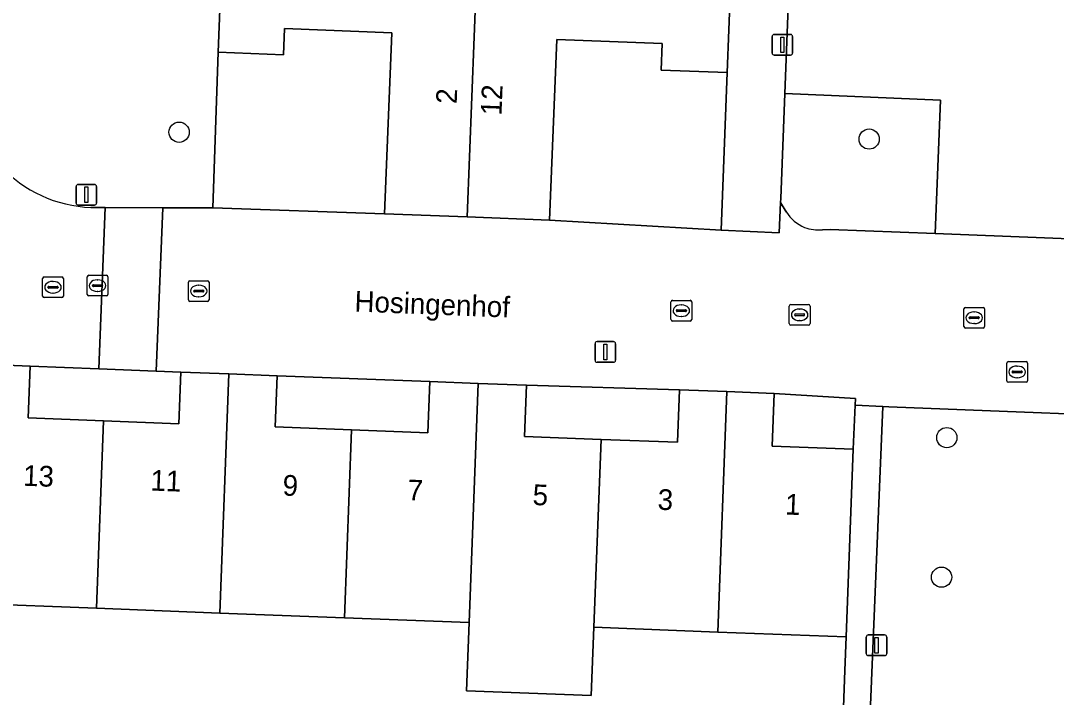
# Model space of a CAD drawing. Extents: x 160786 to 161429, y 386828 to 387485.
# Drawn here: x 161233.9 to 161283.9, y 387191.8 to 387224.5 of the extents above; entities that cross this region are included whole.
import ezdxf

# ---------------------------------------------------------------- set-up
doc = ezdxf.new("R2010")
doc.units = 0
for name, color, linetype in [('IMGEO_Boom', 7, 'Continuous'), ('IMGEO_Brandkraan', 7, 'Continuous'), ('IMGEO_Erf', 7, 'Continuous'), ('IMGEO_Groenvoorziening', 7, 'Continuous'), ('IMGEO_Kolk', 7, 'Continuous'), ('IMGEO_Lichtmast', 7, 'Continuous'), ('IMGEO_Muur', 7, 'Continuous'), ('IMGEO_Openbare_ruimte_label', 7, 'Continuous'), ('IMGEO_Pand', 7, 'Continuous'), ('IMGEO_Pand_nummerreeks', 7, 'Continuous'), ('IMGEO_Rijbaan_lokaal_open', 7, 'Continuous'), ('IMGEO_Rioolput', 7, 'Continuous'), ('IMGEO_Voetpad_open', 7, 'Continuous')]:
    doc.layers.add(name, color=color, linetype=linetype)

msp = doc.modelspace()

# ---------------------------------------------------------------- linework, layer by layer
at = {"layer": 'IMGEO_Boom'}
for centre in [(161241.538, 387219.106), (161274.878, 387218.776), (161278.63, 387204.353), (161278.378, 387197.612)]:
    msp.add_circle(centre, 0.489, dxfattribs=at)
at = {"layer": 'IMGEO_Brandkraan'}
for p, q in [((161281.606, 387208.028), (161282.458, 387208.028)), ((161281.531, 387207.102), (161281.531, 387207.954)), ((161281.79, 387207.522), (161281.79, 387207.534)), ((161281.833, 387207.571), (161282.231, 387207.571)), ((161282.019, 387207.808), (161282.044, 387207.808)), ((161282.274, 387207.534), (161282.274, 387207.522)), ((161282.532, 387207.954), (161282.532, 387207.102)), ((161282.458, 387207.028), (161281.606, 387207.028)), ((161282.228, 387207.485), (161281.83, 387207.485)), ((161282.042, 387207.248), (161282.017, 387207.248))]:
    msp.add_line(p, q, dxfattribs=at)
for points in [[(161281.606, 387208.028), (161282.458, 387208.028)], [(161281.531, 387207.102), (161281.531, 387207.954)], [(161282.532, 387207.954), (161282.532, 387207.102)], [(161282.458, 387207.028), (161281.606, 387207.028)]]:
    msp.add_lwpolyline(points, dxfattribs=at)
for centre, radius, start, end in [((161281.608, 387207.952), 0.0765, 91.552, 178.448), ((161281.608, 387207.952), 0.0765, 91.552, 178.448), ((161282.456, 387207.952), 0.0765, 1.552, 88.448), ((161282.456, 387207.952), 0.0765, 1.552, 88.448), ((161281.83, 387207.531), 0.0403, 85.8775, 175.7526), ((161281.827, 387207.521), 0.0366, 178.938, 274.7102), ((161282.231, 387207.528), 0.043, 264.8664, 352.4533), ((161282.235, 387207.533), 0.0386, 1.7309, 96.639), ((161281.608, 387207.104), 0.0765, 181.552, 268.448), ((161281.608, 387207.104), 0.0765, 181.552, 268.448), ((161282.456, 387207.104), 0.0765, 271.552, 358.448), ((161282.456, 387207.104), 0.0765, 271.552, 358.448)]:
    msp.add_arc(centre, radius, start, end, dxfattribs=at)
for centre, major_axis, ratio, start_param, end_param in [((161282.018, 387207.528), (-0.387, 0.002), 0.722429, 4.712389, 7.853982), ((161282.043, 387207.528), (-0.39, 0.002), 0.717154, 1.570796, 4.712389)]:
    msp.add_ellipse(centre, major_axis=major_axis, ratio=ratio, start_param=start_param, end_param=end_param, dxfattribs=at)
at = {"layer": 'IMGEO_Erf'}
for points in [[(161243.165, 387215.454), (161251.463, 387215.171), (161251.811, 387223.912), (161246.634, 387224.118), (161246.584, 387222.846), (161243.425, 387222.972)], [(161268.013, 387221.984), (161264.831, 387222.111), (161264.882, 387223.389), (161259.784, 387223.592), (161259.437, 387214.853), (161267.73, 387214.375)], [(161237.659, 387207.677), (161234.345, 387207.807), (161234.25, 387205.304), (161237.885, 387205.165), (161241.52, 387205.027), (161241.615, 387207.521), (161240.436, 387207.567)], [(161246.271, 387207.343), (161246.177, 387204.869), (161249.87, 387204.728), (161253.563, 387204.587), (161253.658, 387207.063)], [(161258.322, 387206.886), (161258.228, 387204.411), (161261.925, 387204.27), (161265.618, 387204.13), (161265.715, 387206.665)], [(161274.202, 387205.923), (161274.217, 387206.248), (161270.296, 387206.49), (161270.199, 387203.947), (161274.106, 387203.798)]]:
    msp.add_lwpolyline(points, close=True, dxfattribs=at)
msp.add_lwpolyline([(161273.288, 387181.587), (161273.702, 387193.11), (161273.76, 387194.728), (161267.563, 387194.964), (161261.579, 387195.192), (161261.452, 387191.894), (161255.425, 387192.124), (161255.55, 387195.422), (161249.524, 387195.652), (161243.502, 387195.881), (161237.54, 387196.109), (161231.59, 387196.335)], dxfattribs=at)
at = {"layer": 'IMGEO_Groenvoorziening'}
for points in [[(161302.945, 387270.254), (161272.951, 387271.43), (161272.761, 387271.438), (161270.807, 387220.973), (161278.33, 387220.657), (161278.076, 387214.209), (161299.195, 387213.381)], [(161278.33, 387220.657), (161270.807, 387220.973), (161270.611, 387215.901), (161270.603, 387215.713), (161270.826, 387215.342), (161270.88, 387215.251)], [(161272.624, 387214.392), (161272.998, 387214.408), (161278.076, 387214.209), (161278.33, 387220.657)], [(161291.402, 387205.236), (161275.836, 387205.849), (161275.544, 387205.862), (161274.672, 387184.815), (161274.672, 387184.136), (161274.676, 387183.739), (161274.704, 387183.178)]]:
    msp.add_lwpolyline(points, dxfattribs=at)
for centre, radius, start, end in [((161272.497, 387216.271), 1.912, 212.2414, 247.1627), ((161272.456, 387216.432), 2.047, 249.9626, 274.7013)]:
    msp.add_arc(centre, radius, start, end, dxfattribs=at)
at = {"layer": 'IMGEO_Kolk'}
for p, q in [((161237.097, 387211.272), (161237.097, 387212.124)), ((161237.172, 387212.198), (161238.024, 387212.198)), ((161238.098, 387212.124), (161238.098, 387211.272)), ((161237.356, 387211.692), (161237.356, 387211.704)), ((161237.794, 387211.655), (161237.396, 387211.655)), ((161237.399, 387211.741), (161237.797, 387211.741)), ((161237.585, 387211.978), (161237.61, 387211.978)), ((161237.84, 387211.704), (161237.84, 387211.692)), ((161241.985, 387211.009), (161241.985, 387211.861)), ((161242.06, 387211.935), (161242.912, 387211.935)), ((161242.473, 387211.715), (161242.498, 387211.715)), ((161242.986, 387211.861), (161242.986, 387211.009)), ((161238.024, 387211.198), (161237.172, 387211.198)), ((161237.608, 387211.418), (161237.583, 387211.418)), ((161242.244, 387211.429), (161242.244, 387211.441)), ((161242.682, 387211.392), (161242.284, 387211.392)), ((161242.287, 387211.478), (161242.685, 387211.478)), ((161242.496, 387211.155), (161242.471, 387211.155)), ((161242.728, 387211.441), (161242.728, 387211.429)), ((161242.912, 387210.935), (161242.06, 387210.935)), ((161265.304, 387210.06), (161265.304, 387210.912)), ((161265.379, 387210.986), (161266.231, 387210.986)), ((161265.606, 387210.529), (161266.004, 387210.529)), ((161265.792, 387210.766), (161265.817, 387210.766)), ((161266.305, 387210.912), (161266.305, 387210.06)), ((161265.563, 387210.48), (161265.563, 387210.492)), ((161266.001, 387210.443), (161265.603, 387210.443)), ((161265.815, 387210.206), (161265.79, 387210.206)), ((161266.047, 387210.492), (161266.047, 387210.48)), ((161266.231, 387209.986), (161265.379, 387209.986))]:
    msp.add_line(p, q, dxfattribs=at)
for points in [[(161237.097, 387211.272), (161237.097, 387212.124)], [(161237.172, 387212.198), (161238.024, 387212.198)], [(161238.098, 387212.124), (161238.098, 387211.272)], [(161241.985, 387211.009), (161241.985, 387211.861)], [(161242.06, 387211.935), (161242.912, 387211.935)], [(161242.986, 387211.861), (161242.986, 387211.009)], [(161238.024, 387211.198), (161237.172, 387211.198)], [(161242.912, 387210.935), (161242.06, 387210.935)], [(161265.304, 387210.06), (161265.304, 387210.912)], [(161265.379, 387210.986), (161266.231, 387210.986)], [(161266.305, 387210.912), (161266.305, 387210.06)], [(161266.231, 387209.986), (161265.379, 387209.986)]]:
    msp.add_lwpolyline(points, dxfattribs=at)
for centre, radius, start, end in [((161237.174, 387212.122), 0.0765, 91.552, 178.448), ((161237.174, 387212.122), 0.0765, 91.552, 178.448), ((161238.022, 387212.122), 0.0765, 1.552, 88.448), ((161238.022, 387212.122), 0.0765, 1.552, 88.448), ((161237.396, 387211.701), 0.0403, 85.8775, 175.7526), ((161237.393, 387211.691), 0.0366, 178.938, 274.7102), ((161237.797, 387211.698), 0.043, 264.8664, 352.4533), ((161237.801, 387211.703), 0.0386, 1.7309, 96.639), ((161242.062, 387211.859), 0.0765, 91.552, 178.448), ((161242.062, 387211.859), 0.0765, 91.552, 178.448), ((161242.91, 387211.859), 0.0765, 1.552, 88.448), ((161242.91, 387211.859), 0.0765, 1.552, 88.448), ((161237.174, 387211.274), 0.0765, 181.552, 268.448), ((161237.174, 387211.274), 0.0765, 181.552, 268.448), ((161238.022, 387211.274), 0.0765, 271.552, 358.448), ((161238.022, 387211.274), 0.0765, 271.552, 358.448), ((161242.062, 387211.011), 0.0765, 181.552, 268.448), ((161242.062, 387211.011), 0.0765, 181.552, 268.448), ((161242.284, 387211.438), 0.0403, 85.8775, 175.7526), ((161242.281, 387211.428), 0.0366, 178.938, 274.7102), ((161242.685, 387211.435), 0.043, 264.8664, 352.4533), ((161242.689, 387211.44), 0.0386, 1.7309, 96.639), ((161242.91, 387211.011), 0.0765, 271.552, 358.448), ((161242.91, 387211.011), 0.0765, 271.552, 358.448), ((161265.381, 387210.91), 0.0765, 91.552, 178.448), ((161265.381, 387210.91), 0.0765, 91.552, 178.448), ((161265.603, 387210.489), 0.0403, 85.8775, 175.7526), ((161266.008, 387210.491), 0.0386, 1.7309, 96.639), ((161266.229, 387210.91), 0.0765, 1.552, 88.448), ((161266.229, 387210.91), 0.0765, 1.552, 88.448), ((161265.381, 387210.062), 0.0765, 181.552, 268.448), ((161265.381, 387210.062), 0.0765, 181.552, 268.448), ((161265.6, 387210.479), 0.0366, 178.938, 274.7102), ((161266.004, 387210.486), 0.043, 264.8664, 352.4533), ((161266.229, 387210.062), 0.0765, 271.552, 358.448), ((161266.229, 387210.062), 0.0765, 271.552, 358.448)]:
    msp.add_arc(centre, radius, start, end, dxfattribs=at)
for centre, major_axis, ratio, start_param, end_param in [((161237.584, 387211.698), (-0.387, 0.002), 0.722429, 4.712389, 7.853982), ((161237.609, 387211.698), (-0.39, 0.002), 0.717154, 1.570796, 4.712389), ((161242.472, 387211.435), (-0.387, 0.002), 0.722429, 4.712389, 7.853982), ((161242.497, 387211.435), (-0.39, 0.002), 0.717154, 1.570796, 4.712389), ((161265.791, 387210.486), (-0.387, 0.002), 0.722429, 4.712389, 7.853982), ((161265.816, 387210.486), (-0.39, 0.002), 0.717154, 1.570796, 4.712389)]:
    msp.add_ellipse(centre, major_axis=major_axis, ratio=ratio, start_param=start_param, end_param=end_param, dxfattribs=at)
at = {"layer": 'IMGEO_Lichtmast'}
for p, q in [((161270.19, 387222.931), (161270.19, 387223.731)), ((161270.19, 387223.731), (161270.19, 387222.931)), ((161270.29, 387223.831), (161271.08, 387223.831)), ((161271.08, 387223.831), (161270.29, 387223.831)), ((161271.18, 387223.731), (161271.18, 387222.931)), ((161271.18, 387222.931), (161271.18, 387223.731)), ((161271.08, 387222.831), (161270.29, 387222.831)), ((161270.29, 387222.831), (161271.08, 387222.831)), ((161236.661, 387216.586), (161237.451, 387216.586)), ((161237.451, 387216.586), (161236.661, 387216.586)), ((161236.561, 387215.686), (161236.561, 387216.486)), ((161236.561, 387216.486), (161236.561, 387215.686)), ((161237.551, 387216.486), (161237.551, 387215.686)), ((161237.551, 387215.686), (161237.551, 387216.486)), ((161237.451, 387215.586), (161236.661, 387215.586)), ((161236.661, 387215.586), (161237.451, 387215.586)), ((161261.634, 387208.092), (161261.634, 387208.892)), ((161261.634, 387208.892), (161261.634, 387208.092)), ((161261.734, 387208.992), (161262.524, 387208.992)), ((161262.524, 387208.992), (161261.734, 387208.992)), ((161262.624, 387208.892), (161262.624, 387208.092)), ((161262.624, 387208.092), (161262.624, 387208.892)), ((161262.524, 387207.992), (161261.734, 387207.992)), ((161261.734, 387207.992), (161262.524, 387207.992)), ((161274.738, 387193.923), (161274.738, 387194.723)), ((161274.738, 387194.723), (161274.738, 387193.923)), ((161274.838, 387194.823), (161275.628, 387194.823)), ((161275.628, 387194.823), (161274.838, 387194.823)), ((161275.728, 387194.723), (161275.728, 387193.923)), ((161275.728, 387193.923), (161275.728, 387194.723)), ((161275.628, 387193.823), (161274.838, 387193.823)), ((161274.838, 387193.823), (161275.628, 387193.823))]:
    msp.add_line(p, q, dxfattribs=at)
for points in [[(161270.61, 387223.706), (161270.76, 387223.706), (161270.76, 387222.956), (161270.61, 387222.956), (161270.61, 387223.706)], [(161236.981, 387216.461), (161237.131, 387216.461), (161237.131, 387215.711), (161236.981, 387215.711), (161236.981, 387216.461)], [(161262.054, 387208.867), (161262.204, 387208.867), (161262.204, 387208.117), (161262.054, 387208.117), (161262.054, 387208.867)], [(161275.158, 387194.698), (161275.308, 387194.698), (161275.308, 387193.948), (161275.158, 387193.948), (161275.158, 387194.698)]]:
    msp.add_lwpolyline(points, dxfattribs=at)
for centre, start, end in [((161270.29, 387223.731), 90, 180), ((161270.29, 387223.731), 90, 180), ((161271.08, 387223.731), 0, 90), ((161271.08, 387223.731), 360, 90), ((161270.29, 387222.931), 180, 270), ((161270.29, 387222.931), 180, 270), ((161271.08, 387222.931), 270, 0), ((161271.08, 387222.931), 270, 0), ((161236.661, 387216.486), 90, 180), ((161236.661, 387216.486), 90, 180), ((161237.451, 387216.486), 0, 90), ((161237.451, 387216.486), 360, 90), ((161236.661, 387215.686), 180, 270), ((161236.661, 387215.686), 180, 270), ((161237.451, 387215.686), 270, 0), ((161237.451, 387215.686), 270, 0), ((161261.734, 387208.892), 90, 180), ((161261.734, 387208.892), 90, 180), ((161262.524, 387208.892), 0, 90), ((161262.524, 387208.892), 360, 90), ((161261.734, 387208.092), 180, 270), ((161261.734, 387208.092), 180, 270), ((161262.524, 387208.092), 270, 0), ((161262.524, 387208.092), 270, 0), ((161274.838, 387194.723), 90, 180), ((161274.838, 387194.723), 90, 180), ((161275.628, 387194.723), 0, 90), ((161275.628, 387194.723), 360, 90), ((161274.838, 387193.923), 180, 270), ((161274.838, 387193.923), 180, 270), ((161275.628, 387193.923), 270, 0), ((161275.628, 387193.923), 270, 0)]:
    msp.add_arc(centre, 0.1, start, end, dxfattribs=at)
at = {"layer": 'IMGEO_Muur'}
for points in [[(161243.165, 387215.454), (161243.425, 387222.972)], [(161268.013, 387221.984), (161267.73, 387214.375)], [(161251.463, 387215.171), (161243.165, 387215.454)], [(161259.437, 387214.853), (161267.73, 387214.375)], [(161273.76, 387194.728), (161273.702, 387193.11)]]:
    msp.add_lwpolyline(points, dxfattribs=at)
at = {"layer": 'IMGEO_Pand'}
for points in [[(161255.45, 387215.012), (161255.899, 387226.628), (161251.924, 387226.796), (161243.59, 387227.128), (161243.425, 387222.972), (161246.584, 387222.846), (161246.634, 387224.118), (161251.811, 387223.912), (161251.463, 387215.171)], [(161259.437, 387214.853), (161259.784, 387223.592), (161264.882, 387223.389), (161264.831, 387222.111), (161268.013, 387221.984), (161268.178, 387226.131), (161259.905, 387226.46), (161255.899, 387226.628), (161255.45, 387215.012)], [(161232.03, 387207.895), (161231.59, 387196.335), (161237.54, 387196.109), (161237.885, 387205.165), (161234.25, 387205.304), (161234.345, 387207.807)], [(161241.615, 387207.521), (161241.52, 387205.027), (161237.885, 387205.165), (161237.54, 387196.109), (161243.502, 387195.881), (161243.942, 387207.432)], [(161243.942, 387207.432), (161243.502, 387195.881), (161249.524, 387195.652), (161249.87, 387204.728), (161246.177, 387204.869), (161246.271, 387207.343)], [(161253.658, 387207.063), (161253.563, 387204.587), (161249.87, 387204.728), (161249.524, 387195.652), (161255.55, 387195.422), (161255.99, 387206.975)], [(161261.579, 387195.192), (161261.925, 387204.27), (161258.228, 387204.411), (161258.322, 387206.886), (161255.99, 387206.975), (161255.55, 387195.422), (161255.425, 387192.124), (161261.452, 387191.894)], [(161265.715, 387206.665), (161265.618, 387204.13), (161261.925, 387204.27), (161261.579, 387195.192), (161267.563, 387194.964), (161268.005, 387206.578)], [(161268.005, 387206.578), (161267.563, 387194.964), (161273.76, 387194.728), (161274.106, 387203.798), (161270.199, 387203.947), (161270.296, 387206.49)]]:
    msp.add_lwpolyline(points, close=True, dxfattribs=at)
at = {"layer": 'IMGEO_Rijbaan_lokaal_open'}
for points in [[(161270.88, 387215.251), (161270.826, 387215.342), (161270.603, 387215.713), (161270.538, 387214.251), (161267.73, 387214.375), (161259.437, 387214.853), (161255.45, 387215.012), (161251.463, 387215.171), (161243.165, 387215.454), (161240.747, 387215.462), (161240.436, 387207.567), (161241.615, 387207.521), (161243.942, 387207.432), (161246.271, 387207.343), (161253.658, 387207.063), (161255.99, 387206.975), (161258.322, 387206.886), (161265.715, 387206.665), (161268.005, 387206.578), (161270.296, 387206.49), (161274.217, 387206.248), (161274.202, 387205.923), (161275.544, 387205.862), (161275.836, 387205.849), (161291.402, 387205.236)], [(161232.03, 387207.895), (161234.345, 387207.807), (161237.659, 387207.677), (161237.967, 387215.47), (161237.275, 387215.472)], [(161299.195, 387213.381), (161278.076, 387214.209), (161272.998, 387214.408), (161272.624, 387214.392)]]:
    msp.add_lwpolyline(points, dxfattribs=at)
msp.add_lwpolyline([(161240.747, 387215.462), (161237.967, 387215.47), (161237.659, 387207.677), (161240.436, 387207.567)], close=True, dxfattribs=at)
for centre, radius, start, end in [((161237.517, 387221.748), 6.28, 177.5889, 267.7928), ((161272.497, 387216.271), 1.912, 212.2414, 247.1627), ((161272.456, 387216.432), 2.047, 249.9626, 274.7013)]:
    msp.add_arc(centre, radius, start, end, dxfattribs=at)
at = {"layer": 'IMGEO_Rioolput'}
for p, q in [((161234.944, 387211.192), (161234.944, 387212.044)), ((161235.019, 387212.118), (161235.871, 387212.118)), ((161235.945, 387212.044), (161235.945, 387211.192)), ((161235.203, 387211.612), (161235.203, 387211.624)), ((161235.641, 387211.575), (161235.243, 387211.575)), ((161235.246, 387211.661), (161235.644, 387211.661)), ((161235.432, 387211.898), (161235.457, 387211.898)), ((161235.687, 387211.624), (161235.687, 387211.612)), ((161235.871, 387211.118), (161235.019, 387211.118)), ((161235.455, 387211.338), (161235.43, 387211.338)), ((161271.02, 387209.86), (161271.02, 387210.712)), ((161271.095, 387210.786), (161271.947, 387210.786)), ((161271.508, 387210.566), (161271.533, 387210.566)), ((161272.021, 387210.712), (161272.021, 387209.86)), ((161279.455, 387209.719), (161279.455, 387210.571)), ((161279.53, 387210.645), (161280.382, 387210.645)), ((161280.456, 387210.571), (161280.456, 387209.719)), ((161271.279, 387210.28), (161271.279, 387210.292)), ((161271.717, 387210.243), (161271.319, 387210.243)), ((161271.322, 387210.329), (161271.72, 387210.329)), ((161271.531, 387210.006), (161271.506, 387210.006)), ((161271.763, 387210.292), (161271.763, 387210.28)), ((161279.714, 387210.139), (161279.714, 387210.151)), ((161280.152, 387210.102), (161279.754, 387210.102)), ((161279.757, 387210.188), (161280.155, 387210.188)), ((161279.943, 387210.425), (161279.968, 387210.425)), ((161280.198, 387210.151), (161280.198, 387210.139)), ((161271.947, 387209.786), (161271.095, 387209.786)), ((161280.382, 387209.645), (161279.53, 387209.645)), ((161279.966, 387209.865), (161279.941, 387209.865))]:
    msp.add_line(p, q, dxfattribs=at)
for points in [[(161234.944, 387211.192), (161234.944, 387212.044)], [(161235.019, 387212.118), (161235.871, 387212.118)], [(161235.945, 387212.044), (161235.945, 387211.192)], [(161235.871, 387211.118), (161235.019, 387211.118)], [(161271.02, 387209.86), (161271.02, 387210.712)], [(161271.095, 387210.786), (161271.947, 387210.786)], [(161272.021, 387210.712), (161272.021, 387209.86)], [(161279.455, 387209.719), (161279.455, 387210.571)], [(161279.53, 387210.645), (161280.382, 387210.645)], [(161280.456, 387210.571), (161280.456, 387209.719)], [(161271.947, 387209.786), (161271.095, 387209.786)], [(161280.382, 387209.645), (161279.53, 387209.645)]]:
    msp.add_lwpolyline(points, dxfattribs=at)
for centre, radius, start, end in [((161235.021, 387212.042), 0.0765, 91.552, 178.448), ((161235.021, 387212.042), 0.0765, 91.552, 178.448), ((161235.869, 387212.042), 0.0765, 1.552, 88.448), ((161235.869, 387212.042), 0.0765, 1.552, 88.448), ((161235.243, 387211.621), 0.0403, 85.8775, 175.7526), ((161235.24, 387211.611), 0.0366, 178.938, 274.7102), ((161235.644, 387211.618), 0.043, 264.8664, 352.4533), ((161235.648, 387211.623), 0.0386, 1.7309, 96.639), ((161235.021, 387211.194), 0.0765, 181.552, 268.448), ((161235.021, 387211.194), 0.0765, 181.552, 268.448), ((161235.869, 387211.194), 0.0765, 271.552, 358.448), ((161235.869, 387211.194), 0.0765, 271.552, 358.448), ((161271.097, 387210.71), 0.0765, 91.552, 178.448), ((161271.097, 387210.71), 0.0765, 91.552, 178.448), ((161271.945, 387210.71), 0.0765, 1.552, 88.448), ((161271.945, 387210.71), 0.0765, 1.552, 88.448), ((161279.532, 387210.569), 0.0765, 91.552, 178.448), ((161279.532, 387210.569), 0.0765, 91.552, 178.448), ((161280.38, 387210.569), 0.0765, 1.552, 88.448), ((161280.38, 387210.569), 0.0765, 1.552, 88.448), ((161271.319, 387210.289), 0.0403, 85.8775, 175.7526), ((161271.316, 387210.279), 0.0366, 178.938, 274.7102), ((161271.72, 387210.286), 0.043, 264.8664, 352.4533), ((161271.724, 387210.291), 0.0386, 1.7309, 96.639), ((161279.754, 387210.148), 0.0403, 85.8775, 175.7526), ((161279.751, 387210.138), 0.0366, 178.938, 274.7102), ((161280.155, 387210.145), 0.043, 264.8664, 352.4533), ((161280.159, 387210.15), 0.0386, 1.7309, 96.639), ((161271.097, 387209.862), 0.0765, 181.552, 268.448), ((161271.097, 387209.862), 0.0765, 181.552, 268.448), ((161271.945, 387209.862), 0.0765, 271.552, 358.448), ((161271.945, 387209.862), 0.0765, 271.552, 358.448), ((161279.532, 387209.721), 0.0765, 181.552, 268.448), ((161279.532, 387209.721), 0.0765, 181.552, 268.448), ((161280.38, 387209.721), 0.0765, 271.552, 358.448), ((161280.38, 387209.721), 0.0765, 271.552, 358.448)]:
    msp.add_arc(centre, radius, start, end, dxfattribs=at)
for centre, major_axis, ratio, start_param, end_param in [((161235.431, 387211.618), (-0.387, 0.002), 0.722429, 4.712389, 7.853982), ((161235.456, 387211.618), (-0.39, 0.002), 0.717154, 1.570796, 4.712389), ((161271.507, 387210.286), (-0.387, 0.002), 0.722429, 4.712389, 7.853982), ((161271.532, 387210.286), (-0.39, 0.002), 0.717154, 1.570796, 4.712389), ((161279.942, 387210.145), (-0.387, 0.002), 0.722429, 4.712389, 7.853982), ((161279.967, 387210.145), (-0.39, 0.002), 0.717154, 1.570796, 4.712389)]:
    msp.add_ellipse(centre, major_axis=major_axis, ratio=ratio, start_param=start_param, end_param=end_param, dxfattribs=at)
at = {"layer": 'IMGEO_Voetpad_open'}
for points in [[(161269.755, 387267.338), (161269.563, 387262.328), (161269.482, 387260.218), (161269.314, 387255.996), (161269.024, 387248.648), (161268.861, 387244.561), (161268.595, 387237.411), (161268.428, 387233.219), (161268.178, 387226.131), (161268.013, 387221.984), (161267.73, 387214.375), (161270.538, 387214.251), (161270.603, 387215.713), (161270.611, 387215.901), (161270.807, 387220.973), (161272.761, 387271.438)], [(161237.275, 387215.472), (161237.967, 387215.47), (161240.747, 387215.462), (161243.165, 387215.454), (161243.425, 387222.972), (161243.59, 387227.128), (161243.858, 387234.254), (161244.025, 387238.443), (161244.297, 387245.564), (161244.463, 387249.735), (161244.725, 387257.051)], [(161274.704, 387183.178), (161274.676, 387183.739), (161274.672, 387184.136), (161274.672, 387184.815), (161275.544, 387205.862), (161274.202, 387205.923), (161274.106, 387203.798), (161273.76, 387194.728), (161273.702, 387193.11), (161273.288, 387181.587), (161200.679, 387184.363), (161194.67, 387184.6), (161188.761, 387184.833), (161170.542, 387185.542), (161165.811, 387185.802), (161165.628, 387185.801), (161133.615, 387186.89)]]:
    msp.add_lwpolyline(points, dxfattribs=at)
msp.add_arc((161237.517, 387221.748), 6.28, 177.5889, 267.7928, dxfattribs=at)

# ---------------------------------------------------------------- texts
at = {"layer": 'IMGEO_Openbare_ruimte_label'}
msp.add_text('Hosingenhof', height=1, rotation=357.7644, dxfattribs=at).set_placement((161249.999, 387210.447))
at = {"layer": 'IMGEO_Pand_nummerreeks'}
for s, rotation, p in [('2', 87.7903, (161254.949, 387220.459)), ('12', 87.7593, (161257.113, 387219.906)), ('13', 357.835, (161233.984, 387202.032)), ('11', 357.835, (161240.139, 387201.8)), ('9', 357.835, (161246.524, 387201.559)), ('7', 357.835, (161252.565, 387201.33)), ('5', 357.835, (161258.605, 387201.102)), ('3', 357.835, (161264.646, 387200.874)), ('1', 357.835, (161270.8, 387200.641))]:
    msp.add_text(s, height=1, rotation=rotation, dxfattribs=at).set_placement(p)

doc.saveas('drawing.dxf')
